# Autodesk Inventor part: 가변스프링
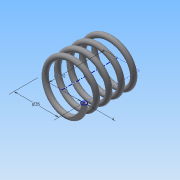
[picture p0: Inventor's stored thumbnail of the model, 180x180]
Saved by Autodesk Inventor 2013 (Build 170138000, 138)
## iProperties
Created: 2015-03
Part Number: 가변스프링
Material: 일반
Document SubType Name: Modeling
Designer: User11
Density: 1 g/cm^3
Author: User11
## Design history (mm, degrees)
sketch "스케치1"
  geometry: L1 (0, 0)-(17.5, 0); L2 (17.5, 0)-(17.5, 43.5); L3 (17.5, 43.5)-(0, 43.5); L4 (0, 43.5)-(0, 0); C1 r 2 at (17.5, 0)
  constraints: 8 end point, 2 parallel, 1 centre point, 1 coincident, 1 horizontal, 1 perpendicular
  dimensions: "d0" = 43.5 distance of L3.end L1.start (derived); "d1" = 35 diameter of L2 L4; "d2" = 4 diameter of C1
feature "코일1" sketch "스케치1" pitch "d3" = 10; turns "d5" = 4.5; dims "d4" = 43.5 (= d0), "d6" = 0, angle "d7" = 90 deg, angle "d8" = 90 deg, "d9" = 0, "d10" = 0
sketch "스케치2"
  geometry: L1 (-19.5, 0)-(-15.5, 0) reference; L2 (-19.5, 0)-(-15.5, 0) reference; 1 further point
  constraints: 2 horizontal alignment
extrude "돌출1" cut sketch "스케치2" stored distance "d11" = 10; taper "d12" = 0 deg
node "작업 평면1"
sketch "스케치3"
  geometry: L1 (15.5, 0)-(19.5, 0) reference; 1 further point
  constraints: 1 horizontal alignment
extrude "돌출2" cut sketch "스케치3" stored distance "d13" = 10; taper "d14" = 0 deg
node "솔리드1"
node "절단 모서리 투영1"
node "절단 모서리 투영2"
node "절단 모서리 투영3"
